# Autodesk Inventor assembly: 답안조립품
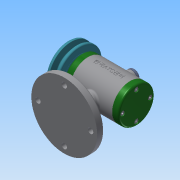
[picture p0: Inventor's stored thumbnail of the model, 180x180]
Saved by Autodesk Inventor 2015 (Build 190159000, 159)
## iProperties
Created: 2018-12
Part Number: 답안조립품
Document SubType Name: Assembly
Designer: 405-15
Author: 405-15
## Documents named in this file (15)
- C:\Users\405-15\Desktop\481207V1052\답안조립품.iam
- C:\Users\405-15\Desktop\481207V1052\본체.ipt
- C:\Users\405-15\Desktop\481207V1052\축.ipt
- C:\Users\405-15\Desktop\481207V1052\키 3 x 3 x 12.ipt
- C:\Users\405-15\Desktop\481207V1052\베어링 15 x 32 x 9.ipt
- C:\Users\405-15\Desktop\481207V1052\뒤커버.ipt
- C:\Users\405-15\Desktop\481207V1052\앞커버.ipt
- C:\Users\405-15\Desktop\481207V1052\오일 실 15 25 7.ipt
- C:\Users\405-15\Desktop\481207V1052\V벨트풀리.ipt
- C:\Users\405-15\Desktop\481207V1052\스프링와셔 8.ipt
- C:\Users\405-15\Desktop\481207V1052\와셔 8x17.ipt
- C:\Users\405-15\Desktop\481207V1052\너트 M8.ipt
- 너트 M8.ipt
- C:\Users\405-15\Desktop\481207V1052\고무캡.ipt
- C:\Users\405-15\Desktop\481207V1052\볼트 M4 x 12.ipt
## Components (2 placed, 2 different names)
1. V벨트풀리:1
2. 고무캡:1 — 각도:2
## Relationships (1: Angle 1)
- 각도:2 [Angle]: 고무캡:1
